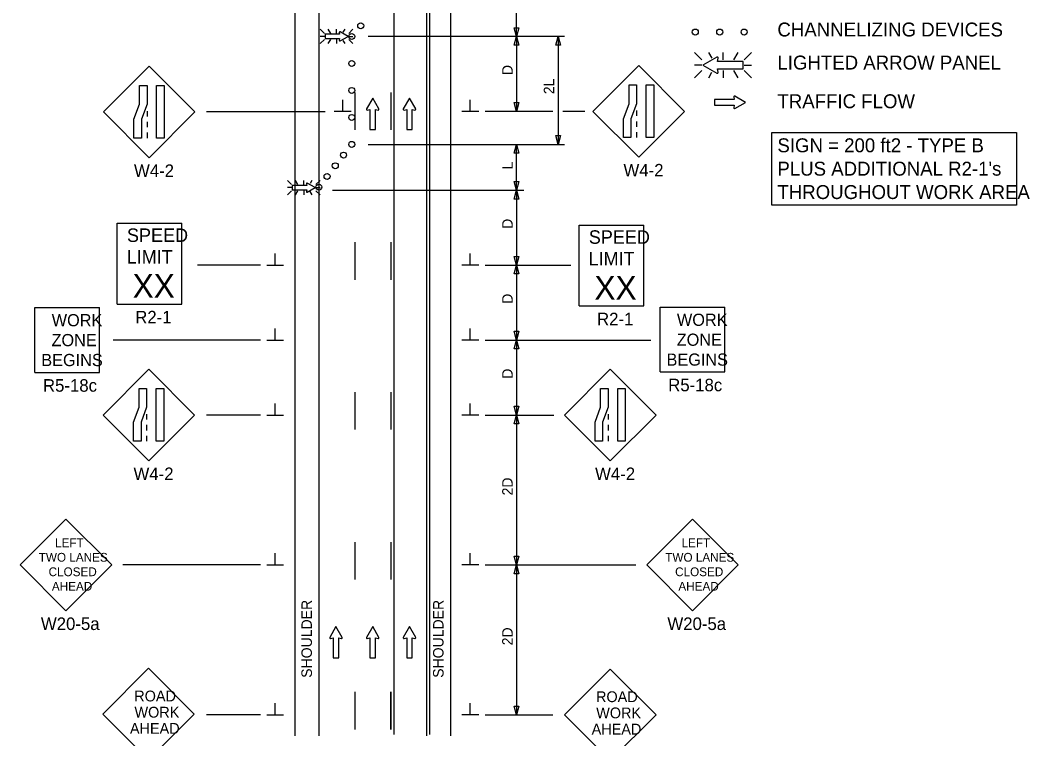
# Model space of a CAD drawing. Extents: x 16745 to 18475, y 6983 to 8234.
# Drawn here: x 16755 to 17429, y 7402 to 7882 of the extents above; entities that cross this region are included whole.
import ezdxf

# ---------------------------------------------------------------- set-up
doc = ezdxf.new("R2010")
doc.units = 0
for name, color, linetype in [('ALI_LEGAL_EX', 7, 'Continuous'), ('MT_SCRATCH_LEVEL_E', 7, 'Continuous'), ('PAVT_EDGE_EX', 7, 'Continuous'), ('TRAFFIC_SIGNS_PR', 7, 'Continuous'), ('TYPICAL_TEXT_DIMEN_EX', 7, 'Continuous'), ('TYPICAL_TEXT_DIMEN_PR', 7, 'Continuous')]:
    doc.layers.add(name, color=color, linetype=linetype)

msp = doc.modelspace()

# ---------------------------------------------------------------- linework, layer by layer
at = {"layer": 'ALI_LEGAL_EX'}
for p, q in [((17004.11, 8234.45), (17004.11, 7405.27)), ((17028.11, 8234.45), (17028.11, 7405.27)), ((17028.11, 8234.45), (17028.11, 7405.27))]:
    msp.add_line(p, q, dxfattribs=at)
for points in [[(16978.13, 7833.65), (16978.13, 7808.65)], [(17002.13, 7833.65), (17002.13, 7808.65)], [(16978.13, 7733.65), (16978.13, 7708.65)], [(17002.13, 7733.65), (17002.13, 7708.65)], [(16978.13, 7633.65), (16978.13, 7608.65)], [(17002.13, 7633.65), (17002.13, 7608.65)], [(16978.13, 7533.65), (16978.13, 7508.65)], [(17002.13, 7533.65), (17002.13, 7508.65)], [(16978.13, 7433.65), (16978.13, 7408.65)], [(17002.13, 7408.65), (17002.13, 7433.65)], [(17002.13, 7433.65), (17002.13, 7408.65)]]:
    msp.add_lwpolyline(points, dxfattribs=at)
at = {"layer": 'MT_SCRATCH_LEVEL_E'}
for p, q in [((16990.1, 7829.81), (16985.98, 7822.57)), ((16994.24, 7822.57), (16990.1, 7829.81)), ((17014.65, 7829.81), (17010.54, 7822.57)), ((17018.8, 7822.57), (17014.65, 7829.81)), ((17231.53, 7828.8), (17218.27, 7828.8)), ((17218.27, 7828.8), (17218.27, 7825.06)), ((17231.22, 7830.58), (17231.53, 7828.8)), ((17239.14, 7826.95), (17231.9, 7831.06)), ((16986.47, 7821.88), (16988.24, 7822.2)), ((16988.24, 7822.2), (16988.24, 7808.94)), ((16991.99, 7808.94), (16991.99, 7822.2)), ((16991.99, 7822.2), (16993.76, 7821.88)), ((17011.03, 7821.88), (17012.8, 7822.2)), ((17012.8, 7822.2), (17012.8, 7808.94)), ((17016.54, 7808.94), (17016.54, 7822.2)), ((17016.54, 7822.2), (17018.32, 7821.88)), ((17218.27, 7825.06), (17231.53, 7825.06)), ((17231.53, 7825.06), (17231.22, 7823.28)), ((17231.9, 7822.8), (17239.14, 7826.95)), ((16988.24, 7808.94), (16991.99, 7808.94)), ((17012.8, 7808.94), (17016.54, 7808.94)), ((16965.57, 7477.28), (16961.46, 7470.04)), ((16969.71, 7470.04), (16965.57, 7477.28)), ((16990.1, 7477.28), (16985.98, 7470.04)), ((16994.24, 7470.04), (16990.1, 7477.28)), ((17014.65, 7477.28), (17010.54, 7470.04)), ((17018.8, 7470.04), (17014.65, 7477.28)), ((16961.94, 7469.36), (16963.71, 7469.67)), ((16963.71, 7469.67), (16963.71, 7456.42)), ((16967.46, 7456.42), (16967.46, 7469.67)), ((16967.46, 7469.67), (16969.23, 7469.36)), ((16986.47, 7469.36), (16988.24, 7469.67)), ((16988.24, 7469.67), (16988.24, 7456.42)), ((16991.99, 7456.42), (16991.99, 7469.67)), ((16991.99, 7469.67), (16993.76, 7469.36)), ((17011.03, 7469.36), (17012.8, 7469.67)), ((17012.8, 7469.67), (17012.8, 7456.42)), ((17016.54, 7456.42), (17016.54, 7469.67)), ((17016.54, 7469.67), (17018.32, 7469.36)), ((16963.71, 7456.42), (16967.46, 7456.42)), ((16988.24, 7456.42), (16991.99, 7456.42)), ((17012.8, 7456.42), (17016.54, 7456.42))]:
    msp.add_line(p, q, dxfattribs=at)
for centre, start, end in [((17231.68, 7830.65), 60.42484, 189.96381), ((16986.39, 7822.34), 150.42484, 279.96381), ((16993.83, 7822.34), 260.03619, 29.77312), ((17010.95, 7822.34), 150.42484, 279.96381), ((17018.39, 7822.34), 260.03619, 29.77312), ((17231.68, 7823.21), 170.03619, 299.77312), ((16961.86, 7469.82), 150.42484, 279.96381), ((16969.3, 7469.82), 260.03619, 29.77312), ((16986.39, 7469.82), 150.42484, 279.96381), ((16993.83, 7469.82), 260.03619, 29.77312), ((17010.95, 7469.82), 150.42484, 279.96381), ((17018.39, 7469.82), 260.03619, 29.77312)]:
    msp.add_arc(centre, 0.463, start, end, dxfattribs=at)
at = {"layer": 'PAVT_EDGE_EX'}
for p, q in [((16938.13, 8183.26), (16938.13, 7404.46)), ((16954.13, 8183.26), (16954.13, 7404.46)), ((17026.13, 8183.26), (17026.13, 7404.46)), ((17042.13, 8183.26), (17042.13, 7404.46))]:
    msp.add_line(p, q, dxfattribs=at)
at = {"layer": 'TRAFFIC_SIGNS_PR'}
for p, q in [((16957.9, 7873.03), (16955.08, 7875.85)), ((16960.2, 7875.85), (16961.83, 7873.03)), ((16965.99, 7873.03), (16965.99, 7875.85)), ((16971.46, 7875.85), (16970.25, 7873.76)), ((16976.89, 7875.85), (16974.07, 7873.03)), ((16957.9, 7871), (16955.08, 7871)), ((16957.9, 7868.97), (16955.08, 7866.15)), ((16961.85, 7868.97), (16960.22, 7866.15)), ((16965.99, 7868.97), (16965.99, 7866.15)), ((16970.17, 7868.33), (16971.43, 7866.15)), ((16974.07, 7871), (16976.89, 7871)), ((16976.89, 7866.15), (16974.07, 7868.97)), ((17204.95, 7860.33), (17209.89, 7855.4)), ((17216.72, 7856.51), (17214.51, 7860.34)), ((17224.04, 7855.4), (17224.04, 7860.34)), ((17231.27, 7855.4), (17234.12, 7860.34)), ((17238.18, 7855.4), (17243.12, 7860.34)), ((16840.86, 7851.17), (16810.31, 7820.63)), ((16871.4, 7820.63), (16840.86, 7851.17)), ((17167.74, 7851.5), (17137.19, 7820.96)), ((17198.28, 7820.96), (17167.74, 7851.5)), ((17209.89, 7851.84), (17204.95, 7851.84)), ((17204.95, 7843.36), (17209.89, 7848.29)), ((17224.04, 7848.29), (17224.04, 7843.35)), ((17234.16, 7843.35), (17231.32, 7848.29)), ((17238.18, 7851.84), (17243.12, 7851.84)), ((17238.18, 7848.29), (17243.12, 7843.35)), ((17214.46, 7843.35), (17216.58, 7847.02)), ((16839.45, 7821.18), (16839.45, 7817.58)), ((17137.19, 7820.96), (17167.74, 7790.41)), ((17166.33, 7821.51), (17166.33, 7817.91)), ((17167.74, 7790.41), (17198.28, 7820.96)), ((16810.31, 7820.63), (16840.86, 7790.08)), ((16840.86, 7790.08), (16871.4, 7820.63)), ((17166.33, 7814.31), (17166.33, 7810.71)), ((16839.45, 7813.98), (16839.45, 7810.38)), ((16839.45, 7806.78), (16839.45, 7803.18)), ((17166.33, 7807.11), (17166.33, 7803.51)), ((16935.96, 7772.11), (16933.14, 7774.93)), ((16938.25, 7774.93), (16939.88, 7772.11)), ((16944.04, 7772.11), (16944.04, 7774.93)), ((16949.51, 7774.93), (16948.3, 7772.84)), ((16954.94, 7774.93), (16952.13, 7772.11)), ((16935.96, 7770.08), (16933.14, 7770.08)), ((16935.96, 7768.04), (16933.14, 7765.22)), ((16939.91, 7768.04), (16938.28, 7765.22)), ((16944.04, 7768.04), (16944.04, 7765.22)), ((16948.22, 7767.41), (16949.49, 7765.22)), ((16952.13, 7770.08), (16954.94, 7770.08)), ((16954.94, 7765.23), (16952.13, 7768.04)), ((16819.52, 7746.39), (16862.72, 7746.39)), ((16819.52, 7692.39), (16819.52, 7746.39)), ((16862.72, 7692.39), (16862.72, 7746.39)), ((17127.92, 7745.15), (17171.12, 7745.15)), ((17127.92, 7691.15), (17127.92, 7745.15)), ((17171.12, 7691.15), (17171.12, 7745.15)), ((16764.51, 7646.82), (16764.51, 7690.02)), ((16764.51, 7690.02), (16807.71, 7690.02)), ((16807.71, 7646.82), (16807.71, 7690.02)), ((16819.52, 7692.39), (16862.72, 7692.39)), ((17127.92, 7691.15), (17171.12, 7691.15)), ((17182.02, 7647.09), (17182.02, 7690.29)), ((17182.02, 7690.29), (17225.22, 7690.29)), ((17225.22, 7647.09), (17225.22, 7690.29)), ((16764.51, 7646.82), (16807.71, 7646.82)), ((16840.56, 7648.94), (16810.01, 7618.39)), ((16871.1, 7618.39), (16840.56, 7648.94)), ((17148.78, 7648.94), (17118.23, 7618.39)), ((17179.32, 7618.39), (17148.78, 7648.94)), ((17182.02, 7647.09), (17225.22, 7647.09)), ((16839.15, 7618.94), (16839.15, 7615.34)), ((17147.37, 7618.94), (17147.37, 7615.34)), ((16810.01, 7618.39), (16840.56, 7587.84)), ((16840.56, 7587.84), (16871.1, 7618.39)), ((17118.23, 7618.39), (17148.78, 7587.84)), ((17148.78, 7587.84), (17179.32, 7618.39)), ((16839.15, 7611.74), (16839.15, 7608.14)), ((17147.37, 7611.74), (17147.37, 7608.14)), ((16839.15, 7604.54), (16839.15, 7600.94)), ((17147.37, 7604.54), (17147.37, 7600.94)), ((16785.25, 7548.91), (16754.7, 7518.36)), ((16815.8, 7518.36), (16785.25, 7548.91)), ((17203.63, 7548.91), (17173.08, 7518.36)), ((17234.17, 7518.36), (17203.63, 7548.91)), ((16754.7, 7518.36), (16785.25, 7487.82)), ((16785.25, 7487.82), (16815.8, 7518.36)), ((17173.08, 7518.36), (17203.63, 7487.82)), ((17203.63, 7487.82), (17234.17, 7518.36)), ((16840.42, 7449.39), (16809.87, 7418.84)), ((16870.96, 7418.84), (16840.42, 7449.39)), ((17148.75, 7448.91), (17118.21, 7418.36)), ((17179.3, 7418.36), (17148.75, 7448.91)), ((16809.87, 7418.84), (16840.42, 7388.3)), ((16840.42, 7388.3), (16870.96, 7418.84)), ((17118.21, 7418.36), (17148.75, 7387.82)), ((17148.75, 7387.82), (17179.3, 7418.36))]:
    msp.add_line(p, q, dxfattribs=at)
for points in [[(16967.81, 7873.68), (16968.04, 7872.39), (16958.32, 7872.39), (16958.32, 7869.64), (16968.04, 7869.64), (16967.81, 7868.34)], [(16968.31, 7867.99), (16973.62, 7871), (16968.31, 7874.04)], [(17219.96, 7857.12), (17210.67, 7851.84), (17219.97, 7846.52)], [(17220.84, 7847.15), (17220.44, 7849.42), (17237.45, 7849.42), (17237.45, 7854.22), (17220.44, 7854.22), (17220.84, 7856.5)], [(16945.87, 7772.76), (16946.1, 7771.46), (16936.38, 7771.46), (16936.38, 7768.72), (16946.1, 7768.72), (16945.87, 7767.41)], [(16946.37, 7767.06), (16951.68, 7770.08), (16946.37, 7773.12)]]:
    msp.add_lwpolyline(points, dxfattribs=at)
for points in [[(16839.45, 7838.33), (16839.45, 7825.75), (16835.69, 7815.76), (16835.69, 7803.18), (16830.64, 7803.18), (16830.64, 7815.76), (16834.4, 7825.75), (16834.4, 7838.33)], [(16850.86, 7838.33), (16850.86, 7803.18), (16845.8, 7803.18), (16845.8, 7838.33)], [(17166.33, 7838.66), (17166.33, 7826.08), (17162.57, 7816.09), (17162.57, 7803.51), (17157.52, 7803.51), (17157.52, 7816.09), (17161.28, 7826.08), (17161.28, 7838.66)], [(17177.74, 7838.66), (17177.74, 7803.51), (17172.68, 7803.51), (17172.68, 7838.66)], [(16839.15, 7636.1), (16839.15, 7623.52), (16835.39, 7613.52), (16835.39, 7600.94), (16830.34, 7600.94), (16830.34, 7613.52), (16834.1, 7623.52), (16834.1, 7636.1)], [(16850.56, 7636.1), (16850.56, 7600.94), (16845.5, 7600.94), (16845.5, 7636.1)], [(17147.37, 7636.1), (17147.37, 7623.52), (17143.61, 7613.52), (17143.61, 7600.94), (17138.56, 7600.94), (17138.56, 7613.52), (17142.32, 7623.52), (17142.32, 7636.1)], [(17158.78, 7636.1), (17158.78, 7600.94), (17153.72, 7600.94), (17153.72, 7636.1)]]:
    msp.add_lwpolyline(points, close=True, dxfattribs=at)
for centre in [(16982.13, 7878.07), (17205.52, 7873.88), (17221.82, 7873.88), (17238.12, 7873.88), (16976.13, 7870.93), (16976.13, 7852.93), (16976.13, 7834.93), (16976.13, 7816.93), (16976.13, 7798.93), (16970.63, 7791.8), (16965.13, 7784.67), (16959.64, 7777.54), (16954.14, 7770.42)]:
    msp.add_circle(centre, 2, dxfattribs=at)
for centre, radius, start, end in [((16968.15, 7873.74), 0.341, 61.48329, 189.95933), ((16968.15, 7868.28), 0.341, 170.73078, 298.89165), ((17220.25, 7856.6), 0.598, 350.73078, 118.89165), ((17220.25, 7847.05), 0.597, 241.48329, 9.95933), ((16946.2, 7772.82), 0.341, 61.48329, 189.95933), ((16946.2, 7767.36), 0.341, 170.73078, 298.89165)]:
    msp.add_arc(centre, radius, start, end, dxfattribs=at)
at = {"layer": 'TYPICAL_TEXT_DIMEN_EX'}
msp.add_lwpolyline([(17256.59, 7806.85), (17419.96, 7806.85), (17419.96, 7758.35), (17256.59, 7758.35)], close=True, dxfattribs=at)
at = {"layer": 'TYPICAL_TEXT_DIMEN_PR'}
for p, q in [((17086.13, 7870.93), (17086.13, 7901.49)), ((17086.13, 7870.93), (17084.56, 7876.79)), ((17084.56, 7876.79), (17086.13, 7876.79)), ((17086.13, 7876.79), (17087.7, 7876.79)), ((17087.7, 7876.79), (17086.13, 7870.93)), ((17118.17, 7870.93), (16987.03, 7870.93)), ((17084.56, 7865.07), (17086.13, 7870.93)), ((17086.13, 7870.93), (17086.13, 7820.93)), ((17086.13, 7870.93), (17087.7, 7865.07)), ((17112.36, 7865.07), (17113.93, 7870.93)), ((17113.93, 7870.93), (17115.5, 7865.07)), ((17113.93, 7870.93), (17113.93, 7798.93)), ((17086.13, 7865.07), (17084.56, 7865.07)), ((17087.7, 7865.07), (17086.13, 7865.07)), ((17113.93, 7865.07), (17112.36, 7865.07)), ((17115.5, 7865.07), (17113.93, 7865.07)), ((16970.05, 7820.93), (16970.05, 7828.71)), ((17055.25, 7820.93), (17055.25, 7828.71)), ((16879.13, 7820.93), (16958.32, 7820.93)), ((16975.68, 7820.93), (16964.43, 7820.93)), ((17060.88, 7820.93), (17049.63, 7820.93)), ((17110.29, 7820.93), (17065.13, 7820.93)), ((17086.13, 7820.93), (17084.56, 7826.79)), ((17084.56, 7826.79), (17086.13, 7826.79)), ((17086.13, 7826.79), (17087.7, 7826.79)), ((17087.7, 7826.79), (17086.13, 7820.93)), ((17113.93, 7825.8), (17113.93, 7822.03)), ((17131.77, 7820.93), (17117.11, 7820.93)), ((17113.93, 7798.93), (17112.36, 7804.79)), ((17112.36, 7804.79), (17113.93, 7804.79)), ((17113.93, 7804.79), (17115.5, 7804.79)), ((17115.5, 7804.79), (17113.93, 7798.93)), ((16987.03, 7798.93), (17118.17, 7798.93)), ((17084.56, 7793.07), (17086.13, 7798.93)), ((17086.13, 7768.36), (17086.13, 7798.93)), ((17086.13, 7798.93), (17087.7, 7793.07)), ((17086.13, 7793.07), (17084.56, 7793.07)), ((17087.7, 7793.07), (17086.13, 7793.07)), ((17086.13, 7768.36), (17084.56, 7774.23)), ((17084.56, 7774.23), (17086.13, 7774.23)), ((17086.13, 7774.23), (17087.7, 7774.23)), ((17087.7, 7774.23), (17086.13, 7768.36)), ((16963.29, 7768.36), (17091.13, 7768.36)), ((17084.56, 7762.5), (17086.13, 7768.36)), ((17086.13, 7768.36), (17086.13, 7718.36)), ((17086.13, 7768.36), (17087.7, 7762.5)), ((17086.13, 7762.5), (17084.56, 7762.5)), ((17087.7, 7762.5), (17086.13, 7762.5)), ((16925, 7718.36), (16925, 7726.15)), ((17055.25, 7718.36), (17055.25, 7726.15)), ((17086.13, 7718.36), (17084.56, 7724.23)), ((17084.56, 7724.23), (17086.13, 7724.23)), ((17086.13, 7724.23), (17087.7, 7724.23)), ((17087.7, 7724.23), (17086.13, 7718.36)), ((16915.13, 7718.36), (16873.19, 7718.36)), ((16919.38, 7718.36), (16930.63, 7718.36)), ((17060.88, 7718.36), (17049.63, 7718.36)), ((17065.13, 7718.36), (17122.38, 7718.36)), ((17084.56, 7712.5), (17086.13, 7718.36)), ((17084.56, 7712.5), (17086.13, 7718.36)), ((17086.13, 7718.36), (17087.7, 7712.5)), ((17086.13, 7718.36), (17086.13, 7668.36)), ((17086.13, 7718.36), (17087.7, 7712.5)), ((17086.13, 7712.5), (17084.56, 7712.5)), ((17086.13, 7712.5), (17084.56, 7712.5)), ((17087.7, 7712.5), (17086.13, 7712.5)), ((17087.7, 7712.5), (17086.13, 7712.5)), ((16925, 7668.36), (16925, 7676.15)), ((17055.25, 7668.36), (17055.25, 7676.15)), ((17086.13, 7668.36), (17084.56, 7674.23)), ((17084.56, 7674.23), (17086.13, 7674.23)), ((17086.13, 7674.23), (17087.7, 7674.23)), ((17087.7, 7674.23), (17086.13, 7668.36)), ((16915.13, 7668.36), (16816.87, 7668.36)), ((16919.38, 7668.36), (16930.63, 7668.36)), ((17060.88, 7668.36), (17049.63, 7668.36)), ((17065.13, 7668.36), (17175.88, 7668.36)), ((17084.56, 7662.5), (17086.13, 7668.36)), ((17086.13, 7668.36), (17087.7, 7662.5)), ((17086.13, 7668.36), (17086.13, 7618.36)), ((17086.13, 7662.5), (17084.56, 7662.5)), ((17087.7, 7662.5), (17086.13, 7662.5)), ((16925, 7618.36), (16925, 7626.15)), ((17055.25, 7618.36), (17055.25, 7626.15)), ((17086.13, 7618.36), (17084.56, 7624.23)), ((17084.56, 7624.23), (17086.13, 7624.23)), ((17086.13, 7624.23), (17087.7, 7624.23)), ((17087.7, 7624.23), (17086.13, 7618.36)), ((16915.13, 7618.36), (16879.13, 7618.36)), ((16919.38, 7618.36), (16930.63, 7618.36)), ((17060.88, 7618.36), (17049.63, 7618.36)), ((17065.13, 7618.36), (17110.97, 7618.36)), ((17084.56, 7612.5), (17086.13, 7618.36)), ((17086.13, 7612.5), (17084.56, 7612.5)), ((17086.13, 7618.36), (17086.13, 7518.36)), ((17086.13, 7618.36), (17087.7, 7612.5)), ((17087.7, 7612.5), (17086.13, 7612.5)), ((16925, 7518.36), (16925, 7526.15)), ((17055.25, 7518.36), (17055.25, 7526.15)), ((17086.13, 7518.36), (17084.56, 7524.23)), ((17084.56, 7524.23), (17086.13, 7524.23)), ((17086.13, 7524.23), (17087.7, 7524.23)), ((17087.7, 7524.23), (17086.13, 7518.36)), ((16915.13, 7518.36), (16823.23, 7518.36)), ((16919.38, 7518.36), (16930.63, 7518.36)), ((17060.88, 7518.36), (17049.63, 7518.36)), ((17065.13, 7518.36), (17165.73, 7518.36)), ((17084.56, 7512.5), (17086.13, 7518.36)), ((17086.13, 7518.36), (17086.13, 7418.36)), ((17086.13, 7518.36), (17087.7, 7512.5)), ((17086.13, 7512.5), (17084.56, 7512.5)), ((17087.7, 7512.5), (17086.13, 7512.5)), ((16925, 7418.36), (16925, 7426.15)), ((17055.25, 7418.36), (17055.25, 7426.15)), ((17086.13, 7418.36), (17084.56, 7424.23)), ((17084.56, 7424.23), (17086.13, 7424.23)), ((17086.13, 7424.23), (17087.7, 7424.23)), ((17087.7, 7424.23), (17086.13, 7418.36)), ((16915.13, 7418.36), (16879.13, 7418.36)), ((16919.38, 7418.36), (16930.63, 7418.36)), ((17060.88, 7418.36), (17049.63, 7418.36)), ((17065.13, 7418.36), (17110.34, 7418.36))]:
    msp.add_line(p, q, dxfattribs=at)

# ---------------------------------------------------------------- texts
at = {"layer": 'TRAFFIC_SIGNS_PR'}
for s, height, p in [('W4-2', 8.37, (16830.68, 7777.21)), ('W4-2', 8.37, (17157.57, 7777.54)), ('SPEED', 9, (16826.01, 7733.85)), ('SPEED', 9, (17134.41, 7732.62)), ('LIMIT', 9, (16825.83, 7719.45)), ('LIMIT', 9, (17134.22, 7718.22)), ('XX', 15.785, (16829.78, 7696.61)), ('XX', 15.785, (17138.17, 7695.38)), ('R2-1', 8.37, (16831.53, 7679.52)), ('R2-1', 8.37, (17139.93, 7678.28)), ('WORK', 8.119, (17193.27, 7677.88)), ('WORK', 8.119, (16775.76, 7677.6)), ('ZONE', 8.119, (16775.63, 7664.32)), ('ZONE', 8.119, (17193.14, 7664.59)), ('BEGINS', 8.119, (16768.8, 7651.03)), ('BEGINS', 8.119, (17186.31, 7651.31)), ('R5-18c', 8.37, (16769.92, 7633.94)), ('R5-18c', 8.37, (17187.44, 7634.22)), ('W4-2', 8.37, (16830.38, 7574.98)), ('W4-2', 8.37, (17138.6, 7574.98)), ('LEFT', 5.85, (16777.98, 7530.22)), ('LEFT', 5.85, (17196.35, 7530.22)), ('TWO LANES', 5.85, (16767.09, 7520.54)), ('TWO LANES', 5.85, (17185.47, 7520.54)), ('CLOSED', 5.85, (16773.68, 7510.87)), ('CLOSED', 5.85, (17192.05, 7510.87)), ('AHEAD', 5.85, (16775.87, 7501.19)), ('AHEAD', 5.85, (17194.24, 7501.19)), ('W20-5a', 8.37, (16768.53, 7474.95)), ('W20-5a', 8.37, (17186.91, 7474.95)), ('ROAD', 7.2, (16830.9, 7427.32)), ('ROAD', 7.2, (17139.24, 7426.84)), ('WORK', 7.2, (16831.02, 7416.52)), ('WORK', 7.2, (17139.36, 7416.04)), ('AHEAD', 7.2, (16828, 7405.72)), ('AHEAD', 7.2, (17136.33, 7405.24))]:
    msp.add_text(s, height=height, dxfattribs=at).set_placement(p)
at = {"layer": 'TYPICAL_TEXT_DIMEN_EX'}
for s, p in [('CHANNELIZING DEVICES', (17260.36, 7870.93)), ('LIGHTED ARROW PANEL', (17260.36, 7848.88)), ('TRAFFIC FLOW', (17260.36, 7823.08)), ('SIGN = 200 ft2 - TYPE B', (17260.36, 7793.68)), ("PLUS ADDITIONAL R2-1's", (17260.36, 7778.08)), ('THROUGHOUT WORK AREA', (17260.36, 7762.48))]:
    msp.add_text(s, height=9.3, dxfattribs=at).set_placement(p)
at = {"layer": 'TYPICAL_TEXT_DIMEN_PR'}
for s, p in [('D', (17083.57, 7845.15)), ('2L', (17111.37, 7832.43)), ('L', (17083.57, 7782.22)), ('D', (17083.57, 7742.58)), ('D', (17083.57, 7692.58)), ('D', (17083.57, 7642.58)), ('2D', (17083.57, 7564.73)), ('SHOULDER', (16949.51, 7443.06)), ('SHOULDER', (17037.41, 7443.06)), ('2D', (17083.57, 7464.73))]:
    msp.add_text(s, height=7, rotation=90, dxfattribs=at).set_placement(p)

doc.saveas('drawing.dxf')
